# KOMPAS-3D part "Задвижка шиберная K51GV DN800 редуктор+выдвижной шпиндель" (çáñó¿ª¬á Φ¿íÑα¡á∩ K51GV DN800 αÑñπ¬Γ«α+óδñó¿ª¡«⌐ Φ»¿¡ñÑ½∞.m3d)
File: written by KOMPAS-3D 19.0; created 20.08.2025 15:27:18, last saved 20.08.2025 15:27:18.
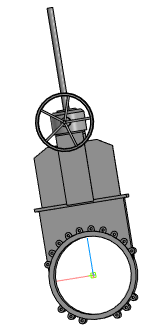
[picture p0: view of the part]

Document properties: Полное имя файла: Задвижка шиберная K51GV DN800 редуктор+выдвижной шпиндель.a3d

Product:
- Part/product: Задвижка шиберная K51GV DN800 редуктор+выдвижной шпиндель
    Масса: 745.473

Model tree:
1. Операция без истории:1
